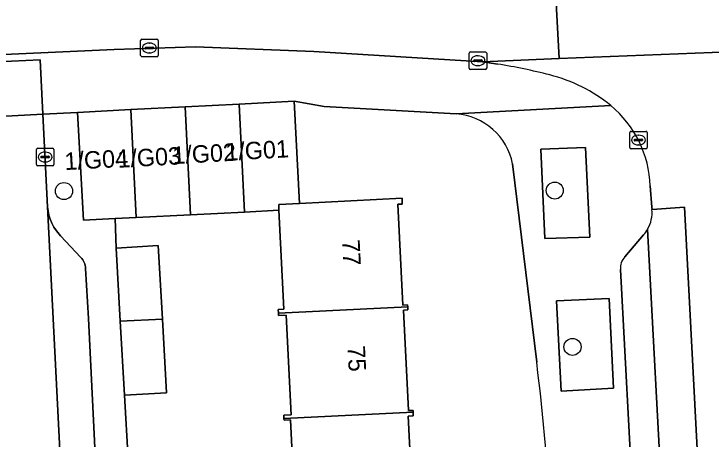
# Model space of a CAD drawing. Extents: x 161084 to 161928, y 385354 to 386522.
# Drawn here: x 161592.17 to 161632.1, y 385728.91 to 385753.28 of the extents above; entities that cross this region are included whole.
import ezdxf

# ---------------------------------------------------------------- set-up
doc = ezdxf.new("R2010")
doc.units = 0
for name, color, linetype in [('IMGEO_Boom', 7, 'Continuous'), ('IMGEO_Erf', 7, 'Continuous'), ('IMGEO_Fietspad_gesloten', 7, 'Continuous'), ('IMGEO_Groenvoorziening', 7, 'Continuous'), ('IMGEO_Kolk', 7, 'Continuous'), ('IMGEO_Pand', 7, 'Continuous'), ('IMGEO_Pand_nummerreeks', 7, 'Continuous'), ('IMGEO_Parkeervlak_open', 7, 'Continuous'), ('IMGEO_Rijbaan_lokaal_gesloten', 7, 'Continuous'), ('IMGEO_Rijbaan_lokaal_open', 7, 'Continuous'), ('IMGEO_Voetpad_open', 7, 'Continuous')]:
    doc.layers.add(name, color=color, linetype=linetype)

msp = doc.modelspace()

# ---------------------------------------------------------------- linework, layer by layer
at = {"layer": 'IMGEO_Boom'}
for centre in [(161595.034, 385743.13), (161623.147, 385743.159), (161624.163, 385734.196)]:
    msp.add_circle(centre, 0.489, dxfattribs=at)
at = {"layer": 'IMGEO_Erf'}
for points in [[(161617.502, 385747.563), (161609.94, 385747.969), (161608.211, 385748.282), (161608.517, 385742.42), (161614.399, 385742.712), (161614.415, 385742.387), (161614.151, 385742.374), (161614.439, 385736.589), (161614.721, 385736.603), (161614.726, 385736.496), (161614.735, 385736.324), (161614.487, 385736.311), (161614.774, 385730.547), (161615.03, 385730.56), (161615.035, 385730.457), (161615.046, 385730.245), (161614.752, 385730.23), (161615.034, 385724.565)], [(161622.112, 385733.314), (161620.733, 385744.68)], [(161608.292, 385724.194), (161608.002, 385730.011), (161607.64, 385729.994), (161607.635, 385730.088), (161607.626, 385730.275), (161608.053, 385730.296), (161607.768, 385736.024), (161607.324, 385736.002), (161607.318, 385736.125), (161607.307, 385736.337), (161607.632, 385736.353), (161607.35, 385742.025), (161605.381, 385741.927), (161602.278, 385741.773), (161599.175, 385741.618), (161597.972, 385741.559), (161598.021, 385739.863), (161600.432, 385740), (161600.672, 385735.792), (161600.914, 385731.559), (161598.503, 385731.422), (161598.703, 385727.765)]]:
    msp.add_lwpolyline(points, dxfattribs=at)
for centre, radius, start, end in [((161617.205, 385743.978), 3.597, 11.2533, 85.262), ((161500.031, 385717.892), 123.051, 2.73634, 7.20003)]:
    msp.add_arc(centre, radius, start, end, dxfattribs=at)
at = {"layer": 'IMGEO_Fietspad_gesloten'}
for points in [[(161634.689, 385664.208), (161632.458, 385706.428), (161631.543, 385723.975), (161630.585, 385742.201), (161628.718, 385742.073)], [(161628.468, 385740.945), (161629.366, 385724.162), (161630.325, 385706.314), (161631.373, 385686.697), (161631.688, 385680.494)]]:
    msp.add_lwpolyline(points, dxfattribs=at)
msp.add_arc((161626.779, 385741.911), 1.945, 330.2295, 4.7774, dxfattribs=at)
at = {"layer": 'IMGEO_Groenvoorziening'}
for points in [[(161625.162, 385740.487), (161624.899, 385745.619), (161622.353, 385745.536), (161622.578, 385740.406)], [(161626.519, 385731.836), (161626.256, 385736.963), (161623.245, 385736.829), (161623.51, 385731.665)]]:
    msp.add_lwpolyline(points, close=True, dxfattribs=at)
at = {"layer": 'IMGEO_Kolk'}
for p, q in [((161599.425, 385750.903), (161599.425, 385751.755)), ((161599.5, 385751.829), (161600.352, 385751.829)), ((161599.913, 385751.609), (161599.938, 385751.609)), ((161600.426, 385751.755), (161600.426, 385750.903)), ((161599.684, 385751.323), (161599.684, 385751.335)), ((161600.122, 385751.286), (161599.724, 385751.286)), ((161599.727, 385751.372), (161600.125, 385751.372)), ((161600.168, 385751.335), (161600.168, 385751.323)), ((161600.352, 385750.829), (161599.5, 385750.829)), ((161599.936, 385751.049), (161599.911, 385751.049)), ((161618.247, 385750.174), (161618.247, 385751.026)), ((161618.322, 385751.1), (161619.174, 385751.1)), ((161618.735, 385750.88), (161618.76, 385750.88)), ((161619.248, 385751.026), (161619.248, 385750.174)), ((161618.506, 385750.594), (161618.506, 385750.606)), ((161618.944, 385750.557), (161618.546, 385750.557)), ((161618.549, 385750.643), (161618.947, 385750.643)), ((161618.758, 385750.32), (161618.733, 385750.32)), ((161618.99, 385750.606), (161618.99, 385750.594)), ((161619.174, 385750.1), (161618.322, 385750.1)), ((161627.44, 385745.626), (161627.44, 385746.478)), ((161627.515, 385746.552), (161628.367, 385746.552)), ((161627.928, 385746.332), (161627.953, 385746.332)), ((161628.441, 385746.478), (161628.441, 385745.626)), ((161627.699, 385746.046), (161627.699, 385746.058)), ((161628.137, 385746.009), (161627.739, 385746.009)), ((161627.742, 385746.095), (161628.14, 385746.095)), ((161628.183, 385746.058), (161628.183, 385746.046)), ((161593.529, 385745.579), (161594.381, 385745.579)), ((161628.367, 385745.552), (161627.515, 385745.552)), ((161627.951, 385745.772), (161627.926, 385745.772)), ((161593.454, 385744.653), (161593.454, 385745.505)), ((161593.756, 385745.122), (161594.154, 385745.122)), ((161593.942, 385745.359), (161593.967, 385745.359)), ((161594.455, 385745.505), (161594.455, 385744.653)), ((161593.713, 385745.073), (161593.713, 385745.085)), ((161594.151, 385745.036), (161593.753, 385745.036)), ((161593.965, 385744.799), (161593.94, 385744.799)), ((161594.197, 385745.085), (161594.197, 385745.073)), ((161594.381, 385744.579), (161593.529, 385744.579))]:
    msp.add_line(p, q, dxfattribs=at)
for points in [[(161599.425, 385750.903), (161599.425, 385751.755)], [(161599.5, 385751.829), (161600.352, 385751.829)], [(161600.426, 385751.755), (161600.426, 385750.903)], [(161600.352, 385750.829), (161599.5, 385750.829)], [(161618.247, 385750.174), (161618.247, 385751.026)], [(161618.322, 385751.1), (161619.174, 385751.1)], [(161619.248, 385751.026), (161619.248, 385750.174)], [(161619.174, 385750.1), (161618.322, 385750.1)], [(161627.44, 385745.626), (161627.44, 385746.478)], [(161627.515, 385746.552), (161628.367, 385746.552)], [(161628.441, 385746.478), (161628.441, 385745.626)], [(161593.529, 385745.579), (161594.381, 385745.579)], [(161628.367, 385745.552), (161627.515, 385745.552)], [(161593.454, 385744.653), (161593.454, 385745.505)], [(161594.455, 385745.505), (161594.455, 385744.653)], [(161594.381, 385744.579), (161593.529, 385744.579)]]:
    msp.add_lwpolyline(points, dxfattribs=at)
for centre, radius, start, end in [((161599.502, 385751.753), 0.0765, 91.552, 178.448), ((161599.502, 385751.753), 0.0765, 91.552, 178.448), ((161600.35, 385751.753), 0.0765, 1.552, 88.448), ((161600.35, 385751.753), 0.0765, 1.552, 88.448), ((161599.724, 385751.332), 0.0403, 85.8775, 175.7526), ((161599.721, 385751.322), 0.0366, 178.938, 274.7102), ((161600.125, 385751.329), 0.043, 264.8664, 352.4533), ((161600.129, 385751.334), 0.0386, 1.7309, 96.639), ((161599.502, 385750.905), 0.0765, 181.552, 268.448), ((161599.502, 385750.905), 0.0765, 181.552, 268.448), ((161600.35, 385750.905), 0.0765, 271.552, 358.448), ((161600.35, 385750.905), 0.0765, 271.552, 358.448), ((161618.324, 385751.024), 0.0765, 91.552, 178.448), ((161618.324, 385751.024), 0.0765, 91.552, 178.448), ((161619.172, 385751.024), 0.0765, 1.552, 88.448), ((161619.172, 385751.024), 0.0765, 1.552, 88.448), ((161618.546, 385750.603), 0.0403, 85.8775, 175.7526), ((161618.543, 385750.593), 0.0366, 178.938, 274.7102), ((161618.947, 385750.6), 0.043, 264.8664, 352.4533), ((161618.951, 385750.605), 0.0386, 1.7309, 96.639), ((161618.324, 385750.176), 0.0765, 181.552, 268.448), ((161618.324, 385750.176), 0.0765, 181.552, 268.448), ((161619.172, 385750.176), 0.0765, 271.552, 358.448), ((161619.172, 385750.176), 0.0765, 271.552, 358.448), ((161627.517, 385746.476), 0.0765, 91.552, 178.448), ((161627.517, 385746.476), 0.0765, 91.552, 178.448), ((161628.365, 385746.476), 0.0765, 1.552, 88.448), ((161628.365, 385746.476), 0.0765, 1.552, 88.448), ((161627.739, 385746.055), 0.0403, 85.8775, 175.7526), ((161627.736, 385746.045), 0.0366, 178.938, 274.7102), ((161628.14, 385746.052), 0.043, 264.8664, 352.4533), ((161628.144, 385746.057), 0.0386, 1.7309, 96.639), ((161593.531, 385745.503), 0.0765, 91.552, 178.448), ((161593.531, 385745.503), 0.0765, 91.552, 178.448), ((161594.379, 385745.503), 0.0765, 1.552, 88.448), ((161594.379, 385745.503), 0.0765, 1.552, 88.448), ((161627.517, 385745.628), 0.0765, 181.552, 268.448), ((161627.517, 385745.628), 0.0765, 181.552, 268.448), ((161628.365, 385745.628), 0.0765, 271.552, 358.448), ((161628.365, 385745.628), 0.0765, 271.552, 358.448), ((161593.753, 385745.082), 0.0403, 85.8775, 175.7526), ((161594.158, 385745.084), 0.0386, 1.7309, 96.639), ((161593.75, 385745.072), 0.0366, 178.938, 274.7102), ((161594.154, 385745.079), 0.043, 264.8664, 352.4533), ((161593.531, 385744.655), 0.0765, 181.552, 268.448), ((161593.531, 385744.655), 0.0765, 181.552, 268.448), ((161594.379, 385744.655), 0.0765, 271.552, 358.448), ((161594.379, 385744.655), 0.0765, 271.552, 358.448)]:
    msp.add_arc(centre, radius, start, end, dxfattribs=at)
for centre, major_axis, ratio, start_param, end_param in [((161599.912, 385751.329), (-0.387, 0.002), 0.722429, 4.712389, 7.853982), ((161599.937, 385751.329), (-0.39, 0.002), 0.717154, 1.570796, 4.712389), ((161618.734, 385750.6), (-0.387, 0.002), 0.722429, 4.712389, 7.853982), ((161618.759, 385750.6), (-0.39, 0.002), 0.717154, 1.570796, 4.712389), ((161627.927, 385746.052), (-0.387, 0.002), 0.722429, 4.712389, 7.853982), ((161627.952, 385746.052), (-0.39, 0.002), 0.717154, 1.570796, 4.712389), ((161593.941, 385745.079), (-0.387, 0.002), 0.722429, 4.712389, 7.853982), ((161593.966, 385745.079), (-0.39, 0.002), 0.717154, 1.570796, 4.712389)]:
    msp.add_ellipse(centre, major_axis=major_axis, ratio=ratio, start_param=start_param, end_param=end_param, dxfattribs=at)
at = {"layer": 'IMGEO_Pand'}
for points in [[(161601.971, 385747.956), (161598.868, 385747.794), (161599.175, 385741.618), (161602.278, 385741.773)], [(161605.072, 385748.118), (161601.971, 385747.956), (161602.278, 385741.773), (161605.381, 385741.927)], [(161608.211, 385748.282), (161605.072, 385748.118), (161605.381, 385741.927), (161607.35, 385742.025), (161607.333, 385742.361), (161608.517, 385742.42)], [(161598.868, 385747.794), (161595.81, 385747.634), (161596.148, 385741.468), (161597.972, 385741.559), (161599.175, 385741.618)], [(161614.151, 385742.374), (161614.415, 385742.387), (161614.399, 385742.712), (161608.517, 385742.42), (161607.333, 385742.361), (161607.35, 385742.025), (161607.632, 385736.353), (161607.307, 385736.337), (161607.318, 385736.125), (161614.726, 385736.496), (161614.721, 385736.603), (161614.439, 385736.589)], [(161598.26, 385735.671), (161600.672, 385735.792), (161600.432, 385740), (161598.021, 385739.863)], [(161607.318, 385736.125), (161607.324, 385736.002), (161607.768, 385736.024), (161608.053, 385730.296), (161607.626, 385730.275), (161607.635, 385730.088), (161615.035, 385730.457), (161615.03, 385730.56), (161614.774, 385730.547), (161614.487, 385736.311), (161614.735, 385736.324), (161614.726, 385736.496)], [(161598.503, 385731.422), (161600.914, 385731.559), (161600.672, 385735.792), (161598.26, 385735.671)], [(161614.752, 385730.23), (161615.046, 385730.245), (161615.035, 385730.457), (161607.635, 385730.088), (161607.64, 385729.994), (161608.002, 385730.011), (161608.292, 385724.194), (161607.963, 385724.177), (161607.969, 385724.049), (161615.345, 385724.418), (161615.337, 385724.58), (161615.034, 385724.565)]]:
    msp.add_lwpolyline(points, close=True, dxfattribs=at)
at = {"layer": 'IMGEO_Parkeervlak_open'}
for points in [[(161597.785, 385708.561), (161596.434, 385735.828), (161596.276, 385738.693), (161596.267, 385738.782), (161596.25, 385738.87), (161596.226, 385738.956), (161596.194, 385739.039), (161596.154, 385739.12), (161596.108, 385739.196), (161596.055, 385739.268), (161596.007, 385739.323), (161594.837, 385740.568), (161594.75, 385740.664), (161594.597, 385740.858), (161594.462, 385741.065), (161594.346, 385741.284), (161594.25, 385741.511), (161594.174, 385741.747), (161594.12, 385741.988), (161594.088, 385742.233), (161596.596, 385692.828)], [(161631.688, 385680.494), (161631.373, 385686.697), (161630.325, 385706.314), (161629.366, 385724.162), (161628.468, 385740.945)], [(161628.238, 385740.624), (161627.162, 385739.353)], [(161626.91, 385738.638), (161627.663, 385724.649), (161628.649, 385706.323), (161629.959, 385682.601)]]:
    msp.add_lwpolyline(points, dxfattribs=at)
for centre, radius, start, end in [((161626.725, 385741.951), 2.013, 318.7492, 330.0067), ((161627.804, 385738.725), 0.899, 135.6353, 185.535)]:
    msp.add_arc(centre, radius, start, end, dxfattribs=at)
at = {"layer": 'IMGEO_Rijbaan_lokaal_gesloten'}
for points in [[(161628.174, 385768.334), (161628.111, 385769.278), (161622.454, 385768.815), (161622.453, 385768.395), (161623.394, 385750.725), (161636.052, 385751.22), (161636.06, 385751.925), (161636.004, 385754.71), (161635.868, 385757.146), (161635.685, 385759.723)], [(161566.659, 385749.814), (161570.507, 385750), (161572.774, 385750.11), (161578.574, 385750.39), (161591.171, 385750.942), (161597.915, 385751.237), (161602.563, 385751.397), (161609.353, 385751.12), (161619.016, 385750.54), (161623.394, 385750.725), (161622.453, 385768.395)], [(161635.984, 385749.703), (161636.038, 385750), (161636.052, 385751.22), (161623.394, 385750.725), (161619.016, 385750.54), (161619.878, 385750.407)], [(161628.616, 385743.422), (161628.705, 385742.211), (161628.718, 385742.073), (161630.585, 385742.201), (161631.543, 385723.975), (161632.458, 385706.428), (161634.689, 385664.208)]]:
    msp.add_lwpolyline(points, dxfattribs=at)
for centre, radius, start, end in [((161614.407, 385716.667), 34.181, 75.6891, 80.7897), ((161620.571, 385740.856), 9.219, 51.1053, 75.6469), ((161622.37, 385743.221), 6.249, 1.8466, 50.3348)]:
    msp.add_arc(centre, radius, start, end, dxfattribs=at)
at = {"layer": 'IMGEO_Rijbaan_lokaal_open'}
msp.add_lwpolyline([(161596.869, 385687.458), (161596.596, 385692.828), (161594.088, 385742.233), (161593.819, 385747.534), (161591.339, 385747.41), (161588.858, 385747.286), (161589.157, 385741.137), (161591.522, 385692.541), (161591.791, 385687.042)], dxfattribs=at)
at = {"layer": 'IMGEO_Voetpad_open'}
for points in [[(161619.878, 385750.407), (161619.016, 385750.54), (161609.353, 385751.12), (161602.563, 385751.397), (161597.915, 385751.237), (161591.171, 385750.942), (161591.191, 385750.529), (161593.672, 385750.646), (161593.819, 385747.534), (161595.81, 385747.634), (161598.868, 385747.794), (161601.971, 385747.956), (161605.072, 385748.118), (161608.211, 385748.282), (161609.94, 385747.969), (161617.502, 385747.563), (161626.359, 385748.031)], [(161626.359, 385748.031), (161617.502, 385747.563)], [(161598.703, 385727.765), (161598.503, 385731.422), (161598.26, 385735.671), (161598.021, 385739.863), (161597.972, 385741.559), (161596.148, 385741.468), (161595.81, 385747.634), (161593.819, 385747.534), (161594.088, 385742.233), (161594.12, 385741.988), (161594.174, 385741.747), (161594.25, 385741.511), (161594.346, 385741.284), (161594.462, 385741.065), (161594.597, 385740.858), (161594.75, 385740.664), (161594.837, 385740.568), (161596.007, 385739.323), (161596.055, 385739.268), (161596.108, 385739.196), (161596.154, 385739.12), (161596.194, 385739.039), (161596.226, 385738.956), (161596.25, 385738.87), (161596.267, 385738.782), (161596.276, 385738.693), (161596.434, 385735.828), (161597.785, 385708.561)], [(161620.733, 385744.68), (161622.112, 385733.314)], [(161628.718, 385742.073), (161628.705, 385742.211), (161628.616, 385743.422)], [(161627.162, 385739.353), (161628.238, 385740.624)], [(161627.663, 385724.649), (161626.91, 385738.638)]]:
    msp.add_lwpolyline(points, dxfattribs=at)
for points in [[(161593.672, 385750.646), (161591.191, 385750.529), (161591.339, 385747.41), (161593.819, 385747.534)], [(161625.162, 385740.487), (161622.578, 385740.406), (161622.353, 385745.536), (161624.899, 385745.619)], [(161623.51, 385731.665), (161623.245, 385736.829), (161626.256, 385736.963), (161626.519, 385731.836)]]:
    msp.add_lwpolyline(points, close=True, dxfattribs=at)
for centre, radius, start, end in [((161614.407, 385716.667), 34.181, 75.6891, 80.7897), ((161620.571, 385740.856), 9.219, 51.1053, 75.6469), ((161622.37, 385743.221), 6.249, 1.8466, 50.3348), ((161617.205, 385743.978), 3.597, 11.2533, 85.262), ((161626.779, 385741.911), 1.945, 330.2295, 4.7774), ((161626.725, 385741.951), 2.013, 318.7492, 330.0067), ((161627.804, 385738.725), 0.899, 135.6353, 185.535), ((161500.031, 385717.892), 123.051, 2.73634, 7.20003)]:
    msp.add_arc(centre, radius, start, end, dxfattribs=at)

# ---------------------------------------------------------------- texts
at = {"layer": 'IMGEO_Pand_nummerreeks'}
for s, rotation, p in [('1/G01', 3.1914, (161604.306, 385744.863)), ('1/G04', 3.1914, (161595.093, 385744.328)), ('1/G03', 3.1914, (161598.126, 385744.461)), ('1/G02', 3.1914, (161601.272, 385744.669)), ('77', 272.8646, (161610.97, 385740.321)), ('75', 272.8671, (161611.274, 385734.243))]:
    msp.add_text(s, height=1, rotation=rotation, dxfattribs=at).set_placement(p)

doc.saveas('drawing.dxf')
